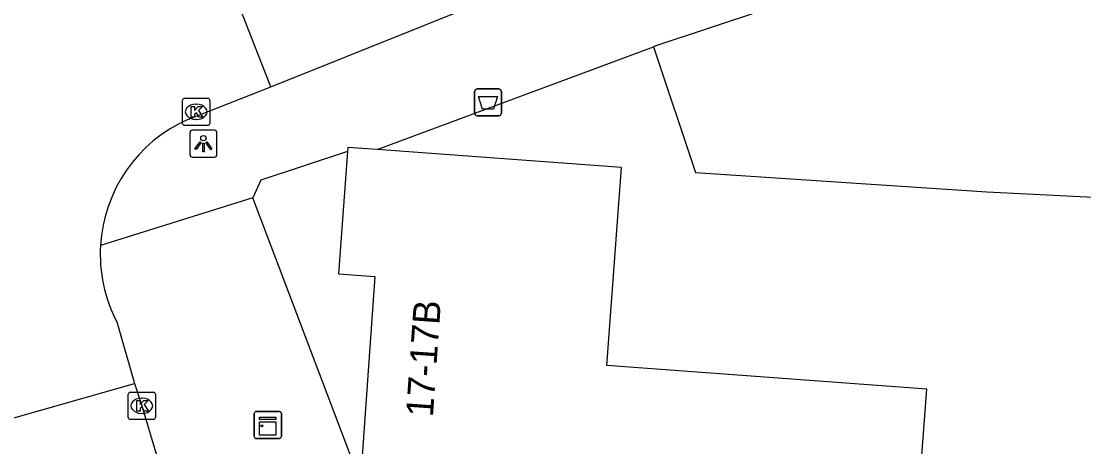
# Model space of a CAD drawing. Extents: x 161087 to 161922, y 382574 to 383873.
# Drawn here: x 161714.55 to 161753.78, y 382798.99 to 382814.7 of the extents above; entities that cross this region are included whole.
import ezdxf

# ---------------------------------------------------------------- set-up
doc = ezdxf.new("R2010")
doc.units = 0
for name, color, linetype in [('IMGEO_Afvalbak', 7, 'Continuous'), ('IMGEO_Kast', 7, 'Continuous'), ('IMGEO_Kolk', 7, 'Continuous'), ('IMGEO_Lichtpunt', 7, 'Continuous'), ('IMGEO_Pand', 7, 'Continuous'), ('IMGEO_Pand_nummerreeks', 7, 'Continuous'), ('IMGEO_Rijbaan_lokaal_gesloten', 7, 'Continuous'), ('IMGEO_Rijbaan_lokaal_open', 7, 'Continuous'), ('IMGEO_Voetpad_open', 7, 'Continuous')]:
    doc.layers.add(name, color=color, linetype=linetype)

msp = doc.modelspace()

# ---------------------------------------------------------------- linework, layer by layer
at = {"layer": 'IMGEO_Afvalbak'}
for p, q in [((161731.289, 382811.309), (161731.289, 382812.109)), ((161731.289, 382812.109), (161731.289, 382811.309)), ((161731.389, 382812.209), (161732.179, 382812.209)), ((161732.179, 382812.209), (161731.389, 382812.209)), ((161732.279, 382812.109), (161732.279, 382811.309)), ((161732.279, 382811.309), (161732.279, 382812.109)), ((161732.179, 382811.209), (161731.389, 382811.209)), ((161731.389, 382811.209), (161732.179, 382811.209))]:
    msp.add_line(p, q, dxfattribs=at)
msp.add_lwpolyline([(161731.432, 382811.923), (161732.136, 382811.923), (161731.987, 382811.453), (161731.581, 382811.453), (161731.432, 382811.923)], dxfattribs=at)
for centre, start, end in [((161731.389, 382812.109), 90, 180), ((161731.389, 382812.109), 90, 180), ((161732.179, 382812.109), 0, 90), ((161732.179, 382812.109), 360, 90), ((161731.389, 382811.309), 180, 270), ((161731.389, 382811.309), 180, 270), ((161732.179, 382811.309), 270, 0), ((161732.179, 382811.309), 270, 0)]:
    msp.add_arc(centre, 0.1, start, end, dxfattribs=at)
at = {"layer": 'IMGEO_Kast'}
for p, q in [((161723.153, 382799.368), (161723.153, 382800.209)), ((161723.153, 382800.209), (161723.153, 382799.368)), ((161723.228, 382800.293), (161724.069, 382800.293)), ((161724.069, 382800.293), (161723.228, 382800.293)), ((161724.153, 382800.218), (161724.153, 382799.377)), ((161724.153, 382799.377), (161724.153, 382800.218)), ((161724.078, 382799.293), (161723.237, 382799.293)), ((161723.237, 382799.293), (161724.078, 382799.293))]:
    msp.add_line(p, q, dxfattribs=at)
for points in [[(161723.348, 382800.083), (161723.948, 382800.083), (161723.948, 382799.998), (161723.348, 382799.998), (161723.348, 382800.083)], [(161723.348, 382799.908), (161723.948, 382799.908), (161723.948, 382799.419), (161723.348, 382799.419), (161723.348, 382799.908)]]:
    msp.add_lwpolyline(points, dxfattribs=at)
msp.add_circle((161723.432, 382799.757), 0.0377, dxfattribs=at)
for centre, start, end in [((161723.231, 382800.215), 92.4484, 184.2845), ((161723.231, 382800.215), 92.4484, 184.2845), ((161724.075, 382800.215), 2.4484, 94.2845), ((161724.075, 382800.215), 2.4484, 94.2845), ((161723.231, 382799.371), 182.4484, 274.2845), ((161723.231, 382799.371), 182.4484, 274.2845), ((161724.075, 382799.371), 272.4484, 4.2845), ((161724.075, 382799.371), 272.4484, 4.2845)]:
    msp.add_arc(centre, 0.0779, start, end, dxfattribs=at)
at = {"layer": 'IMGEO_Kolk'}
for p, q in [((161720.507, 382810.933), (161720.507, 382811.785)), ((161720.582, 382811.859), (161721.434, 382811.859)), ((161720.995, 382811.639), (161721.02, 382811.639)), ((161721.508, 382811.785), (161721.508, 382810.933)), ((161721.434, 382810.859), (161720.582, 382810.859)), ((161721.018, 382811.079), (161720.993, 382811.079)), ((161718.574, 382800.999), (161719.426, 382800.999)), ((161718.499, 382800.073), (161718.499, 382800.925)), ((161718.987, 382800.779), (161719.012, 382800.779)), ((161719.5, 382800.925), (161719.5, 382800.073)), ((161719.01, 382800.219), (161718.985, 382800.219)), ((161719.426, 382799.999), (161718.574, 382799.999))]:
    msp.add_line(p, q, dxfattribs=at)
for points in [[(161720.507, 382810.933), (161720.507, 382811.785)], [(161720.582, 382811.859), (161721.434, 382811.859)], [(161720.828, 382811.559), (161720.951, 382811.559), (161720.951, 382811.408), (161721.081, 382811.559), (161721.245, 382811.559), (161721.099, 382811.408), (161721.252, 382811.159), (161721.1, 382811.159), (161721.015, 382811.323), (161720.951, 382811.256), (161720.951, 382811.159), (161720.828, 382811.159), (161720.828, 382811.559)], [(161721.508, 382811.785), (161721.508, 382810.933)], [(161721.434, 382810.859), (161720.582, 382810.859)], [(161718.574, 382800.999), (161719.426, 382800.999)], [(161718.499, 382800.073), (161718.499, 382800.925)], [(161718.82, 382800.699), (161718.943, 382800.699), (161718.943, 382800.548), (161719.073, 382800.699), (161719.237, 382800.699), (161719.091, 382800.548), (161719.244, 382800.299), (161719.092, 382800.299), (161719.007, 382800.463), (161718.943, 382800.396), (161718.943, 382800.299), (161718.82, 382800.299), (161718.82, 382800.699)], [(161719.5, 382800.925), (161719.5, 382800.073)], [(161719.426, 382799.999), (161718.574, 382799.999)]]:
    msp.add_lwpolyline(points, dxfattribs=at)
for centre, start, end in [((161720.584, 382811.783), 91.552, 178.448), ((161720.584, 382811.783), 91.552, 178.448), ((161721.432, 382811.783), 1.552, 88.448), ((161721.432, 382811.783), 1.552, 88.448), ((161720.584, 382810.935), 181.552, 268.448), ((161720.584, 382810.935), 181.552, 268.448), ((161721.432, 382810.935), 271.552, 358.448), ((161721.432, 382810.935), 271.552, 358.448), ((161718.576, 382800.923), 91.552, 178.448), ((161718.576, 382800.923), 91.552, 178.448), ((161719.424, 382800.923), 1.552, 88.448), ((161719.424, 382800.923), 1.552, 88.448), ((161718.576, 382800.075), 181.552, 268.448), ((161718.576, 382800.075), 181.552, 268.448), ((161719.424, 382800.075), 271.552, 358.448), ((161719.424, 382800.075), 271.552, 358.448)]:
    msp.add_arc(centre, 0.0765, start, end, dxfattribs=at)
for centre, major_axis, ratio, start_param, end_param in [((161720.994, 382811.359), (-0.387, 0.002), 0.722429, 4.712389, 7.853982), ((161721.019, 382811.359), (-0.39, 0.002), 0.717154, 1.570796, 4.712389), ((161718.986, 382800.499), (-0.387, 0.002), 0.722429, 4.712389, 7.853982), ((161719.011, 382800.499), (-0.39, 0.002), 0.717154, 1.570796, 4.712389)]:
    msp.add_ellipse(centre, major_axis=major_axis, ratio=ratio, start_param=start_param, end_param=end_param, dxfattribs=at)
at = {"layer": 'IMGEO_Lichtpunt'}
for p, q in [((161720.776, 382810.587), (161720.776, 382809.78)), ((161720.776, 382810.587), (161720.776, 382809.78)), ((161721.678, 382810.682), (161720.87, 382810.682)), ((161721.678, 382810.682), (161720.87, 382810.682)), ((161721.772, 382809.78), (161721.772, 382810.587)), ((161721.772, 382809.78), (161721.772, 382810.587)), ((161720.87, 382809.686), (161721.678, 382809.686)), ((161720.87, 382809.686), (161721.678, 382809.686))]:
    msp.add_line(p, q, dxfattribs=at)
for points in [[(161721.15, 382810.251), (161721.189, 382810.223), (161721.001, 382809.961), (161720.963, 382809.988), (161721.15, 382810.251)], [(161721.252, 382810.203), (161721.299, 382810.203), (161721.299, 382809.881), (161721.252, 382809.881), (161721.252, 382810.203)], [(161721.362, 382810.223), (161721.4, 382810.25), (161721.587, 382809.988), (161721.548, 382809.96), (161721.362, 382810.223)]]:
    msp.add_lwpolyline(points, dxfattribs=at)
msp.add_circle((161721.275, 382810.385), 0.0994, dxfattribs=at)
for centre, start, end in [((161720.87, 382810.587), 90, 180), ((161720.87, 382810.587), 90, 180), ((161721.678, 382810.587), 0, 90), ((161721.678, 382810.587), 0, 90), ((161720.87, 382809.78), 180, 270), ((161720.87, 382809.78), 180, 270), ((161721.678, 382809.78), 270, 0), ((161721.678, 382809.78), 270, 360)]:
    msp.add_arc(centre, 0.0946, start, end, dxfattribs=at)
at = {"layer": 'IMGEO_Pand'}
for points in [[(161741.914, 382815.103), (161737.983, 382813.795), (161737.9, 382813.764)], [(161737.9, 382813.764), (161739.444, 382809.112), (161750.203, 382808.397), (161758.096, 382808.012), (161757.768, 382809.112), (161758.841, 382809.432), (161760.805, 382810.018), (161760.931, 382809.597)], [(161727.689, 382809.965), (161726.608, 382810.044), (161726.597, 382809.897)], [(161726.597, 382809.897), (161726.265, 382805.37), (161727.605, 382805.272), (161727.116, 382798.288), (161728.994, 382798.175), (161728.891, 382795.986)], [(161742.018, 382796.286), (161747.633, 382796.387), (161747.982, 382801.117), (161736.174, 382801.983), (161736.711, 382809.303), (161727.689, 382809.965)]]:
    msp.add_lwpolyline(points, dxfattribs=at)
at = {"layer": 'IMGEO_Rijbaan_lokaal_gesloten'}
for points in [[(161723.765, 382812.28), (161720.925, 382819.562)], [(161723.765, 382812.28), (161737.856, 382817.95)]]:
    msp.add_lwpolyline(points, dxfattribs=at)
at = {"layer": 'IMGEO_Rijbaan_lokaal_open'}
for points in [[(161720.694, 382811.072), (161723.765, 382812.28)], [(161718.074, 382803.602), (161718.727, 382801.324)], [(161713.481, 382799.83), (161718.727, 382801.324)], [(161718.727, 382801.324), (161719, 382800.499), (161719.906, 382797.448), (161720.902, 382794.586), (161722.993, 382789.011)]]:
    msp.add_lwpolyline(points, dxfattribs=at)
for centre, radius, start, end in [((161722.904, 382806.103), 5.439, 113.9781, 176.6008), ((161722.908, 382806.103), 5.443, 176.6057, 207.3536)]:
    msp.add_arc(centre, radius, start, end, dxfattribs=at)
at = {"layer": 'IMGEO_Voetpad_open'}
for points in [[(161727.689, 382809.965), (161737.9, 382813.764)], [(161726.597, 382809.897), (161723.395, 382808.829), (161723.098, 382808.178)], [(161723.098, 382808.178), (161717.475, 382806.425)], [(161728.324, 382795.075), (161728.007, 382795.96), (161727.726, 382795.98), (161726.794, 382798.437), (161723.098, 382808.178)]]:
    msp.add_lwpolyline(points, dxfattribs=at)

# ---------------------------------------------------------------- texts
at = {"layer": 'IMGEO_Pand_nummerreeks'}
msp.add_text('17-17B', height=1, rotation=85.9952, dxfattribs=at).set_placement((161729.747, 382800.063))

doc.saveas('drawing.dxf')
